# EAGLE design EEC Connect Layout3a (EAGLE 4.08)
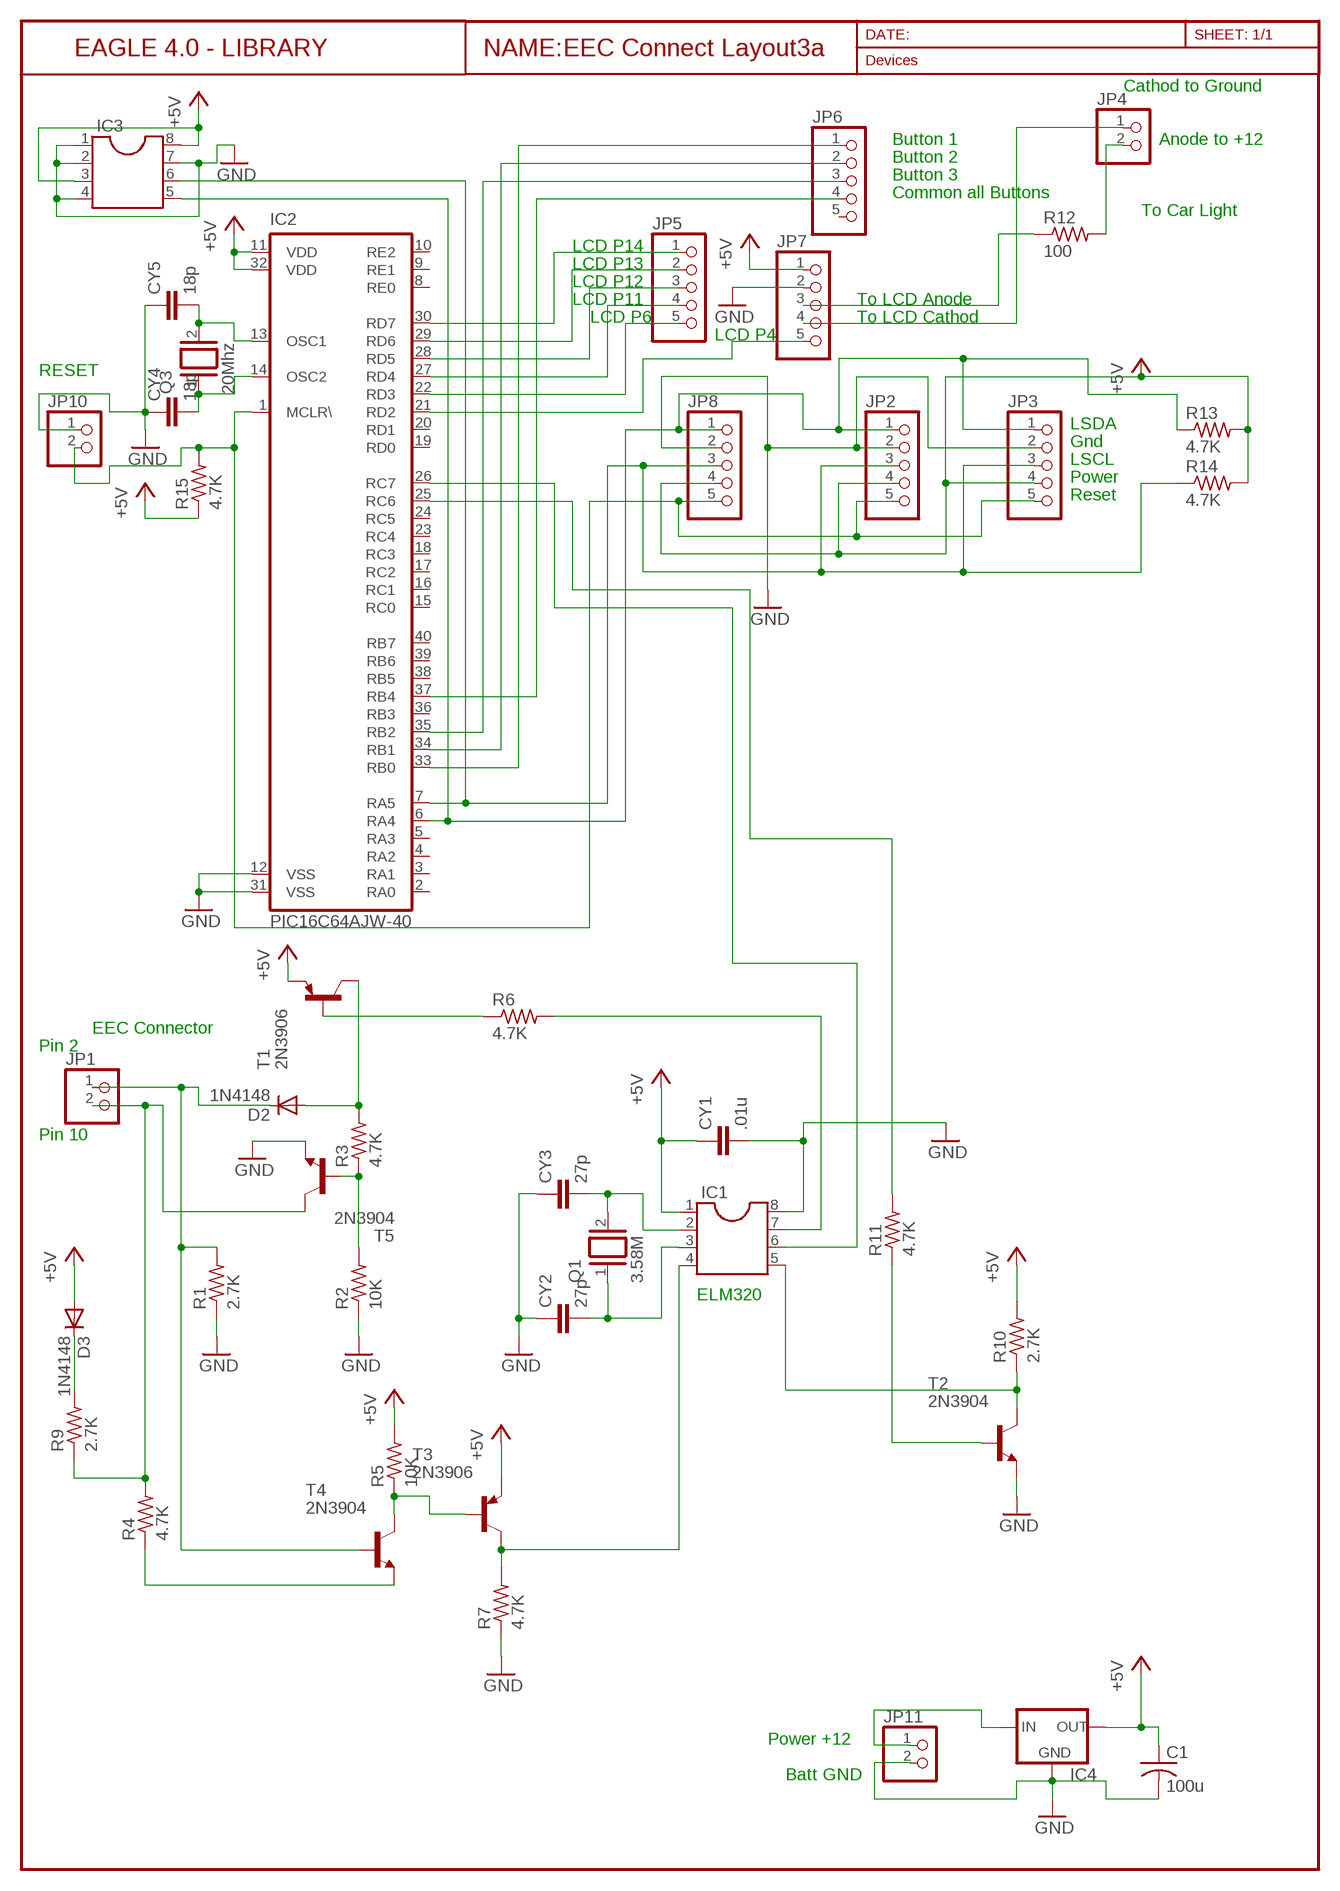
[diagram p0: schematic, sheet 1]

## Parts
C1  100u  C-US050-025X075  [C050-025X075]
CY1  .01u  CYYC7B5  [YC7B5]
CY2  27p  CYYC7B5  [YC7B5]
CY3  27p  CYYC7B5  [YC7B5]
CY4  18p  CYYC7B5  [YC7B5]
CY5  18p  CYYC7B5  [YC7B5]
D2  1N4148  [DO35-10]
D3  1N4148  [DO35-10]
IC1  DIL8  [DIL08]
IC2  PIC16C64AJW-40  [DIL40]
IC3  DIL8  [DIL08]
IC4  78XXL  [78XXL]
JP1  PINHD-1X2  [1X02]
JP2  PINHD-1X5  [1X05]
JP3  PINHD-1X5  [1X05]
JP4  PINHD-1X2  [1X02]
JP5  PINHD-1X5  [1X05]
JP6  PINHD-1X5  [1X05]
JP7  PINHD-1X5  [1X05]
JP8  PINHD-1X5  [1X05]
JP10  PINHD-1X2  [1X02]
JP11  PINHD-1X2  [1X02]
Q1  3.58M  XTAL/S  [QS]
Q3  20Mhz  XTAL/S  [QS]
R1  2.7K  R-US_0207/10  [0207/10]
R2  10K  R-US_0207/10  [0207/10]
R3  4.7K  R-US_0207/10  [0207/10]
R4  4.7K  R-US_0207/10  [0207/10]
R5  10K  R-US_0207/10  [0207/10]
R6  4.7K  R-US_0207/10  [0207/10]
R7  4.7K  R-US_0207/10  [0207/10]
R9  2.7K  R-US_0207/10  [0207/10]
R10  2.7K  R-US_0207/10  [0207/10]
R11  4.7K  R-US_0207/10  [0207/10]
R12  100  R-US_0204/7  [0204/7]
R13  4.7K  R-US_0204/7  [0204/7]
R14  4.7K  R-US_0204/7  [0204/7]
R15  4.7K  R-US_0204/7  [0204/7]
T1  2N3906  [TO92]
T2  2N3904  [TO92]
T3  2N3906  [TO92]
T4  2N3904  [TO92]
T5  2N3904  [TO92]

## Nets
+5V: C1.1 CY1.1 D3.A IC1.1 IC2.11(VDD) IC2.32(VDD) IC3.3 IC3.8 IC4.OUT JP2.4 JP3.4 JP7.1 JP8.4 R5.2 R10.2 R13.2 R14.2 R15.1 T1.3(E) T3.3(E)
GND: C1.2 CY1.2 CY2.1 CY3.1 CY4.1 CY5.1 IC1.8 IC2.12(VSS) IC2.31(VSS) IC3.1 IC3.2 IC3.4 IC3.7 IC4.GND JP2.2 JP3.2 JP7.2 JP8.2 JP10.1 JP11.2 R1.1 R2.1 R7.1 T2.3(E) T5.3(E)
N$1: CY5.2 IC2.13(OSC1) Q3.2
N$2: R2.2 R3.1 T5.2(B)
N$3: D2.C JP1.1 R1.2 T4.2(B)
N$4: IC1.4 R7.2 T3.1(C)
N$5: CY3.2 IC1.2 Q1.2
N$6: CY2.2 IC1.3 Q1.1
N$7: JP4.1 JP7.4
N$8: CY4.2 IC2.14(OSC2) Q3.1
N$9: D3.C R9.2
N$10: R4.1 T4.3(E)
N$11: R5.1 T3.2(B) T4.1(C)
N$12: IC2.37(RB4) JP6.4
N$13: JP4.2 R12.2
N$14: IC2.6(RA4) IC3.5 JP2.1 JP3.1 JP8.1 R13.1
N$15: IC1.7 R6.2
N$16: R6.1 T1.2(B)
N$17: D2.A R3.2 T1.1(C)
N$18: IC2.33(RB0) JP6.1
N$19: JP1.2 R4.2 R9.1 T5.1(C)
N$20: JP7.3 R12.1
N$21: IC2.34(RB1) JP6.2
N$23: IC2.7(RA5) IC3.6 JP2.3 JP3.3 JP8.3 R14.1
N$24: IC2.35(RB2) JP6.3
N$25: IC2.30(RD7) JP5.1
N$27: IC2.29(RD6) JP5.2
N$28: IC2.28(RD5) JP5.3
N$30: IC2.27(RD4) JP5.4
N$31: IC2.22(RD3) JP5.5
N$33: IC2.1(MCLR\) JP2.5 JP3.5 JP8.5 JP10.2 R15.2
N$35: IC2.21(RD2) JP7.5
N$36: R11.1 T2.2(B)
N$40: IC1.5 R10.1 T2.1(C)
N$42: IC4.IN JP11.1
N$45: IC2.25(RC6) R11.2
N$46: IC1.6 IC2.26(RC7)
Unconnected: IC2.2(RA0) IC2.3(RA1) IC2.4(RA2) IC2.5(RA3) IC2.8(RE0) IC2.9(RE1) IC2.10(RE2) IC2.15(RC0) IC2.16(RC1) IC2.17(RC2) IC2.18(RC3) IC2.19(RD0) IC2.20(RD1) IC2.23(RC4) IC2.24(RC5) IC2.36(RB3) IC2.38(RB5) IC2.39(RB6) IC2.40(RB7) JP6.5

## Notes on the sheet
- Cathod to Ground
- Button 1 | Anode to +12
- Button 2
- Button 3
- Common all Buttons
- To Car Light
- LCD P14
- LCD P13
- LCD P12
- LCD P11 | To LCD Anode
- LCD P6 | To LCD Cathod
- LCD P4
- RESET
- LSDA
- Gnd
- LSCL
- Power
- Reset
- EEC Connector
- Pin 2
- Pin 10
- ELM320
- Power +12
- Batt GND

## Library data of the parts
C1 = rcl:C-US: CAPACITOR, American symbol
CY1-CY5 = rcl:CY: Y CAPACITOR
D2 D3 = diode:1N4148: DIODE
IC1 IC3 = dil:DIL8: SOCKET Dual In Line
IC2 = microchip:PIC16C*?-40: MICROCONTROLLER 8-Bit CMOS Pin compatible: PIC16CR64, PIC16C64A, PIC16C65A, PIC16CR65, PIC16C67, PIC16C74A, PIC16C77
IC4 = v-reg:78XXL: VOLTAGE REGULATOR
JP1 JP4 JP10 JP11 = pinhead:PINHD-1X2: PIN HEADER
JP2 JP3 JP5-JP8 = pinhead:PINHD-1X5: PIN HEADER
Q1 Q3 = special:XTAL/S: CRYSTAL
R1-R7 R9-R15 = rcl:R-US_: RESISTOR, American symbol
T1 T3 = transistor-pnp:2N3906: PNP TRANSISTOR
T2 T4 T5 = transistor-npn:2N3904: NPN TRANSISTOR

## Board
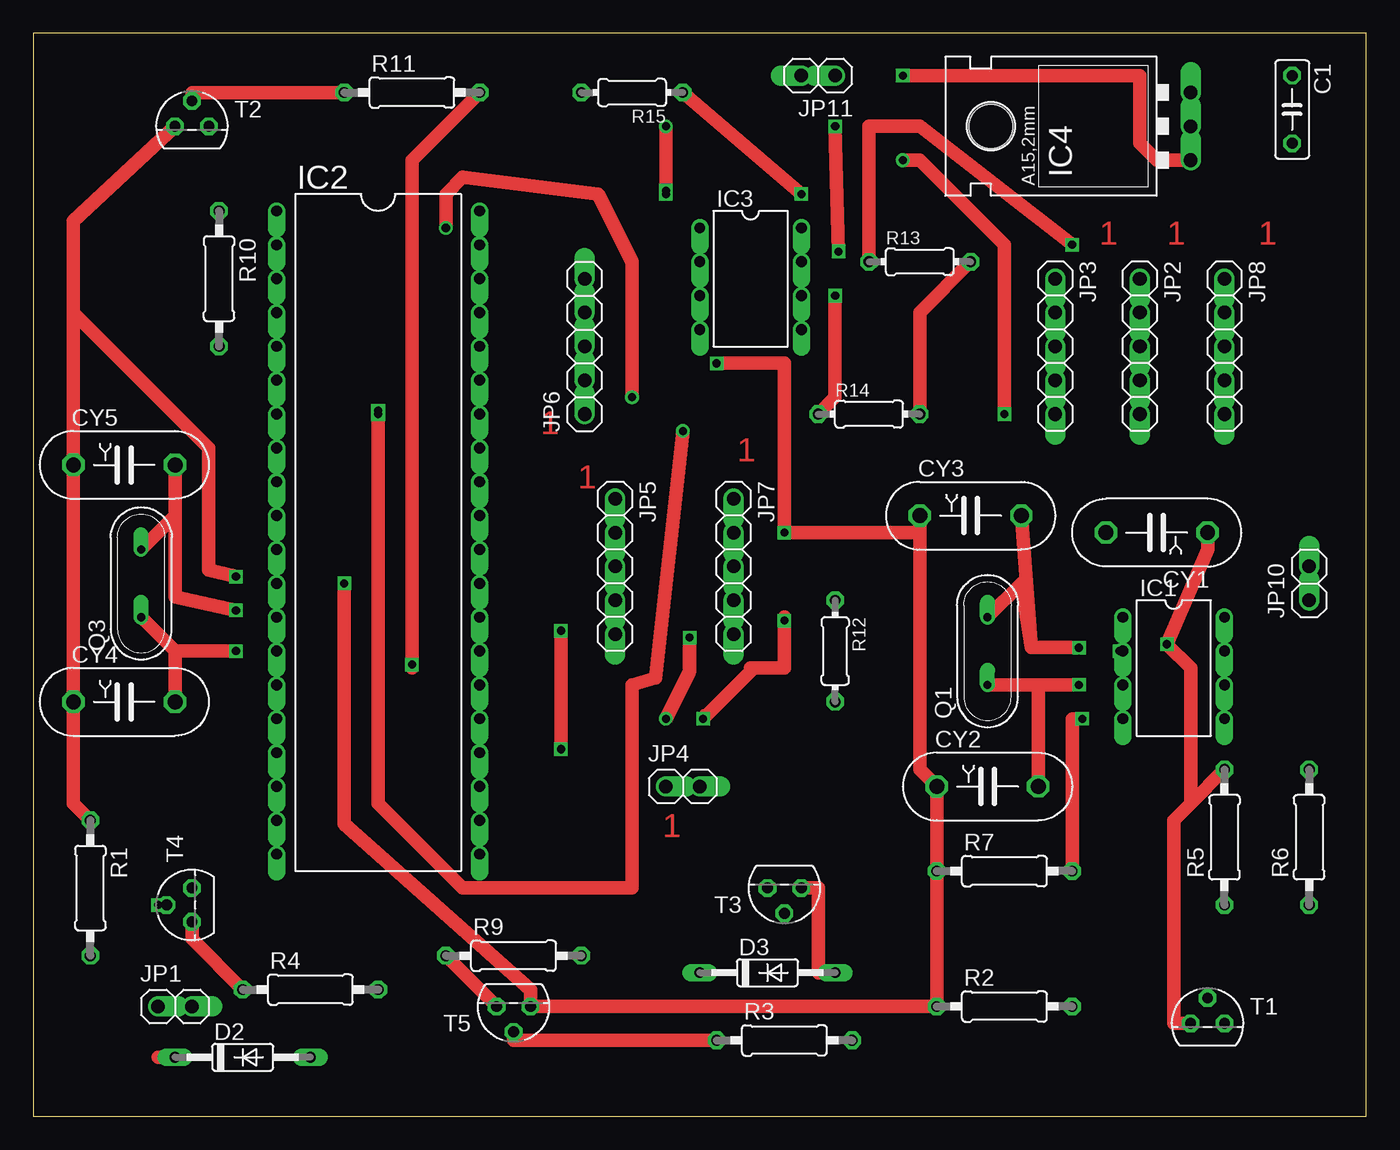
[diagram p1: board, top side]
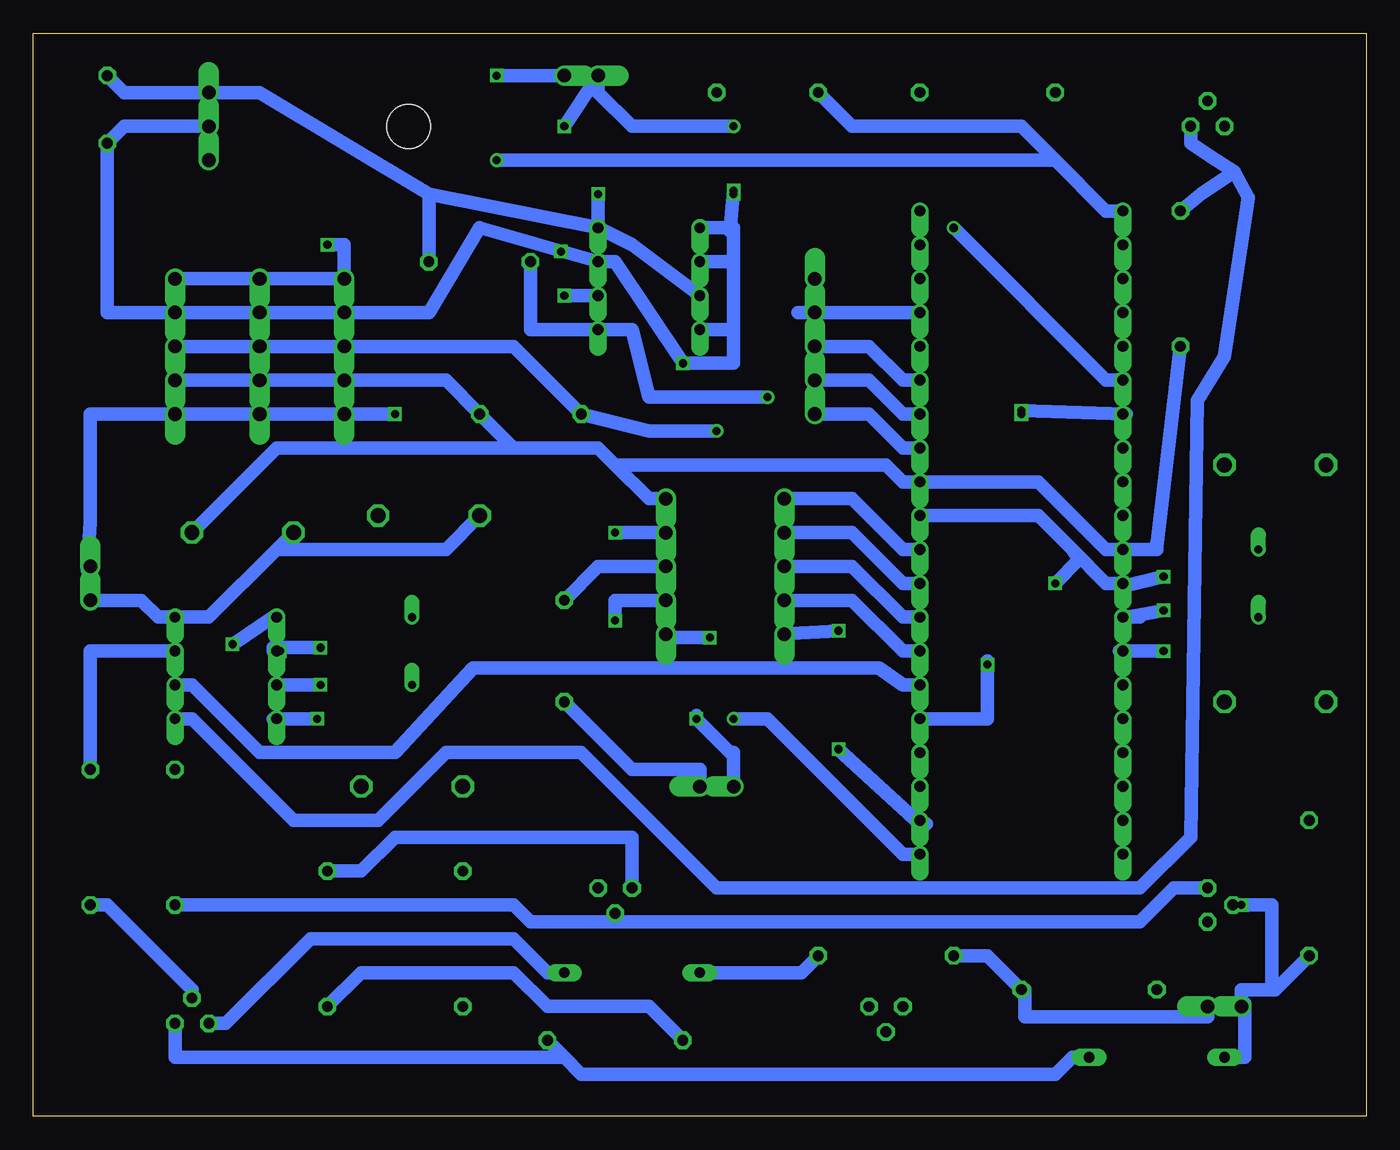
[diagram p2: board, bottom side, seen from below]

Size 100 x 81.27 mm. Coordinates in mm from the lower left corner, seen from the top.
Outline: 0,0 100,0 100,81.27 0,81.27 0,0
Copper layers used: Top, Bottom

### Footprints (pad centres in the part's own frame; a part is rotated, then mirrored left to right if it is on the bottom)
C050-025X075 = drill 0.813 octagon: 1 -2.54,0; 2 2.54,0
YC7B5 = drill 1.118 octagon: 1 -3.81,0; 2 3.81,0
DO35-10 = drill 0.813 long: A 5.08,0; C -5.08,0
DIL08 = drill 0.813 offset: 1 -3.81,-3.81; 2 -1.27,-3.81; 3 1.27,-3.81; 4 3.81,-3.81; 5 3.81,3.81; 6 1.27,3.81; 7 -1.27,3.81; 8 -3.81,3.81
DIL40 = drill 0.813 offset: 1 -24.13,-7.62; 2 -21.59,-7.62; 3 -19.05,-7.62; 4 -16.51,-7.62; 5 -13.97,-7.62; 6 -11.43,-7.62; 7 -8.89,-7.62; 8 -6.35,-7.62; 9 -3.81,-7.62; 10 -1.27,-7.62; 11 1.27,-7.62; 12 3.81,-7.62; 13 6.35,-7.62; 14 8.89,-7.62; 15 11.43,-7.62; 16 13.97,-7.62; 17 16.51,-7.62; 18 19.05,-7.62; 19 21.59,-7.62; 20 24.13,-7.62; 21 24.13,7.62; 22 21.59,7.62; 23 19.05,7.62; 24 16.51,7.62; 25 13.97,7.62; 26 11.43,7.62; 27 8.89,7.62; 28 6.35,7.62; 29 3.81,7.62; 30 1.27,7.62; 31 -1.27,7.62; 32 -3.81,7.62; 33 -6.35,7.62; 34 -8.89,7.62; 35 -11.43,7.62; 36 -13.97,7.62; 37 -16.51,7.62; 38 -19.05,7.62; 39 -21.59,7.62; 40 -24.13,7.62
78XXL = drill 1.016 offset: GND 0,-3.81; IN -2.54,-3.81; OUT 2.54,-3.81 | hole 3.302: 0,11.176
1X02 = drill 1.016 offset: 1 -1.27,0; 2 1.27,0
1X05 = drill 1.016 offset: 1 -5.08,0; 2 -2.54,0; 3 0,0; 4 2.54,0; 5 5.08,0
QS = drill 0.61 offset: 1 -2.54,0; 2 2.54,0
0207/10 = drill 0.813 octagon: 1 -5.08,0; 2 5.08,0
0204/7 = drill 0.813 octagon: 1 -3.81,0; 2 3.81,0
TO92 = drill 0.813 octagon: 1 1.27,0; 2 0,1.905; 3 -1.27,0

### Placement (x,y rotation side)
C1  94.45,75.56 270 top
CY1  84.29,43.81 180 top
CY2  71.59,24.76 0 top
CY3  70.32,45.08 0 top
CY4  6.82,31.11 0 top
CY5  6.82,48.89 0 top
D2  15.71,4.44 0 top
D3  55.08,10.79 0 top
IC1  85.56,33.65 270 top
IC2  25.87,43.81 270 top
IC3  53.81,62.86 270 top
IC4  83.02,74.29 90 top
JP1  10.63,8.25 0 top
JP2  83.02,57.78 270 top
JP3  76.67,57.78 270 top
JP4  48.73,24.76 0 top
JP5  43.65,41.27 270 top
JP6  41.36,57.78 90 top
JP7  52.54,41.27 270 top
JP8  89.37,57.78 270 top
JP10  95.72,40 90 top
JP11  58.89,78.1 180 top
Q1  71.59,34.92 90 top
Q3  8.09,40 90 top
R1  4.28,17.14 270 top
R2  72.86,8.25 0 top
R3  56.35,5.71 0 top
R4  20.79,9.52 0 top
R5  89.37,20.95 90 top
R6  95.72,20.95 90 top
R7  72.86,18.41 0 top
R9  36.03,12.06 0 top
R10  13.93,62.86 270 top
R11  28.41,76.83 0 top
R12  60.16,34.92 270 top
R13  66.51,64.13 0 top
R14  62.7,52.7 0 top
R15  44.92,76.83 180 top
T1  88.1,6.98 0 top
T2  11.9,74.29 0 top
T3  56.35,17.14 180 top
T4  11.9,15.87 90 top
T5  36.03,8.25 180 top

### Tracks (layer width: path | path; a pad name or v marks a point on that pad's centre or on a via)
+5V  (via drill 0.61)
  Top 1.016: CY1.1 88.1,42.54 v85.05,35.43 86.83,33.65 86.83,23.49 | T3.3 58.89,17.14 58.89,10.79 D3.A | T1.3 85.56,6.98 85.56,22.22 86.83,23.49 | 86.83,23.49 R5.2 | v57.62,69.21 R15.1 | R13.2 66.51,60.32 R14.2
  Bottom 1.016: T1.3 85.56,6.98 79.21,13.33 63.97,13.33 61.43,10.79 D3.A | IC3.3 55.08,65.4 IC3.8 | C1.1 93.18,76.83 IC4.OUT 83.02,76.83 70.32,69.21 | 56.35,48.89 57.62,50.16 63.97,50.16 | 56.35,48.89 53.81,46.35 JP7.1 | 63.97,50.16 R14.2 69.05,55.24 JP3.4 JP2.4 JP8.4 | R13.2 70.32,69.21 | 70.32,69.21 IC3.8 | 56.35,48.89 36.03,48.89 34.76,47.62 IC2.32 24.6,47.62 19.52,42.54 IC2.11 15.71,42.54 15.71,42.79 | CY1.1 81.75,50.16 63.97,50.16 | IC3.8 v57.62,69.21 | IC1.1 82,37.46 v85.05,35.43 | 15.71,42.79 15.71,43.05 | 15.71,42.79 R10.2
GND  (via drill 0.61)
  Top 1.016: R1.1 3.01,23.49 CY4.1 CY5.1 3.01,60.32 | T2.3 3.01,67.18 3.01,60.32 | 3.01,60.32 13.17,50.16 13.17,41.02 v15.2,40.51 | 66.51,43.81 v56.35,43.81 56.35,56.51 v51.27,56.51 | 66.51,43.81 CY3.1 | 66.51,43.81 66.51,26.03 CY2.1 R7.1 R2.1 T5.3 37.3,9.52 23.33,21.97 v23.33,40 | v47.46,69.46 v47.46,74.29 | v60.16,74.29 60.41,64.89
  Bottom 1.016: 22.06,42.54 19.52,40 IC2.12 18.25,39.75 v15.2,40.51 | 22.06,42.54 24.6,45.08 IC2.31 | IC4.GND 93.18,74.29 C1.2 94.45,60.32 JP8.2 JP2.2 JP3.2 70.32,60.32 66.51,66.67 IC3.7 56.35,64.13 v51.27,56.51 47.46,56.51 47.46,59.05 | JP10.1 91.91,38.73 90.64,37.46 IC1.8 86.83,37.46 81.75,42.54 | 81.75,42.54 CY1.2 | CY3.1 69.05,42.54 81.75,42.54 | v60.16,74.29 JP11.2 57.62,76.83 55.08,74.29 v47.46,74.29 | 47.46,66.67 IC3.1 | 47.46,64.13 47.46,66.67 | 47.46,59.05 IC3.4 | 47.46,64.13 IC3.2 | 47.46,59.05 47.46,64.13 | v47.46,69.46 47.71,66.42 47.46,66.67 | v23.33,40 21.55,41.78 22.06,42.54 | v56.35,43.81 JP7.2
N$1  (via drill 0.61)
  Top 1.016: 10.63,45.08 Q3.2 | 10.63,45.08 CY5.2 | 10.63,45.08 10.63,38.98 v15.2,37.97
  Bottom 1.016: 16.98,37.46 18,37.46 17.01,37.64 | v15.2,37.97 17.01,37.64 | 16.98,37.46 IC2.13 | 17.01,37.64 16.98,37.46
N$2
  Top 1.016: R3.1 36.03,5.71 T5.2
  Bottom 1.016: R2.2 75.4,10.79 63.97,10.79 61.43,8.25 53.81,8.25 R3.1
N$3  (via drill 0.61)
  Top 1.016: D2.C 9.36,4.44 | v9.36,15.87 T4.2
  Bottom 1.016: R1.2 6.82,9.52 7.07,9.52 | 7.07,9.52 9.36,9.52 JP1.1 9.11,8.25 | v9.36,15.87 7.07,15.87 7.07,9.52 | 9.11,8.25 9.11,8.5 | 9.11,8.25 9.11,4.44 D2.C
N$4  (via drill 0.61)
  Top 1.016: R7.2 77.94,29.84 v78.7,29.84
  Bottom 1.016: T3.1 55.08,20.95 72.86,20.95 75.4,18.41 R7.2 | 82,29.84 IC1.4 v78.7,29.84
N$5  (via drill 0.61)
  Top 1.016: Q1.2 74.13,40 74.89,35.17 | 74.89,35.17 CY3.2 | v81.5,34.92 IC1.2 | 74.89,35.17 v78.45,35.17
  Bottom 1.016: v81.5,34.92 82,34.92 82,35.17 v78.45,35.17
N$6  (via drill 0.61)
  Top 1.016: 75.4,32.38 Q1.1 | 75.4,32.38 v78.45,32.38 | CY2.2 75.4,32.38
  Bottom 1.016: v78.45,32.38 IC1.3 81.75,32.13
N$7  (via drill 0.61)
  Top 0.406: 53.81,33.65 53.81,33.9 | v50.25,29.84 50.25,30.35
  Top 1.016: 54.06,33.65 56.35,33.65 v56.35,37.21 56.35,37.46 | v50.25,29.84 54.06,33.65 | 54.06,33.65 53.81,33.65
  Bottom 0.406: 47.46,27.05 47.21,27.3 47.46,27.3 47.71,27.3
  Bottom 1.016: 56.35,37.46 v56.35,37.21 56.35,38.73 JP7.4 | 47.46,27.05 47.46,27.3 JP4.1 | 47.71,27.3 v50.25,29.84 50.25,30.09
N$8  (via drill 0.61)
  Top 1.016: 10.63,34.92 Q3.1 | CY4.2 10.63,34.92 | 10.63,34.92 v15.2,34.92
  Bottom 1.016: 18.5,34.92 IC2.14 v15.2,34.92
N$9
  Bottom 1.016: R9.2 42.38,10.79 D3.C
N$10
  Top 1.016: R4.1 11.9,13.33 T4.3
N$11
  Bottom 1.016: 56.35,14.6 62.7,14.6 63.97,15.87 R5.1 | T4.1 14.44,17.14 16.98,14.6 56.35,14.6 | 56.35,14.6 T3.2
N$12
  Bottom 1.016: 42.63,60.32 JP6.4 IC2.37
N$13
  Bottom 1.016: R12.2 55.08,26.03 50,26.03 JP4.2
N$14  (via drill 0.61)
  Top 1.016: v30.95,66.67 30.95,69.21 32.22,70.48 42.38,69.21 44.92,64.13 v44.92,53.97 | v77.94,65.4 66.51,74.29 62.7,74.29 R13.1
  Bottom 1.016: v30.95,66.67 19.52,55.24 IC2.6 | v44.92,53.97 53.81,53.97 55.08,59.05 IC3.5 62.7,59.05 R13.1 | JP8.1 JP2.1 JP3.1 76.67,65.4 v77.94,65.4
N$15
  Bottom 1.016: R6.2 95.72,34.92 IC1.7
N$16
  Bottom 1.016: R6.1 94.45,15.87 88.1,9.52 T1.2
N$17
  Bottom 1.016: 60.16,4.44 R3.2 | 60.16,4.44 58.89,3.17 23.33,3.17 22.06,4.44 D2.A | T1.1 89.37,4.44 60.16,4.44
N$18
  Bottom 1.016: IC2.33 34.76,50.16 37.3,52.7 JP6.1
N$19
  Top 1.016: R9.1 T5.1
  Bottom 1.016: R9.1 28.41,12.06 R4.2 25.62,9.52 25.62,7.49 11.9,7.49 JP1.2
N$20
  Bottom 1.016: R12.1 57.62,41.27 JP7.3
N$21
  Bottom 1.016: IC2.34 34.76,52.7 37.3,55.24 JP6.2
N$22  (via drill 0.61)
  other vias: 60.41,64.89
N$23  (via drill 0.61)
  Top 1.016: v48.73,51.43 46.7,32.89 44.92,32.38 44.92,17.14 32.22,17.14 25.87,23.49 v25.87,52.95 | v60.16,61.59 60.16,53.97 R14.1
  Bottom 1.016: v48.73,51.43 53.81,51.43 R14.1 63.97,57.78 JP3.3 JP2.3 JP8.3 | v60.16,61.59 IC3.6 | IC2.7 18,52.7 v25.87,52.95
N$24
  Bottom 1.016: IC2.35 34.76,55.24 37.3,57.78 JP6.3
N$25
  Bottom 1.016: IC2.30 34.76,42.54 38.57,46.35 JP5.1
N$26  (via drill 0.61)
  other vias: 47.46,69.21
N$27
  Bottom 1.016: IC2.29 34.76,40 38.57,43.81 JP5.2
N$28
  Bottom 1.016: IC2.28 34.76,37.46 38.57,41.27 JP5.3
N$29  (via drill 0.61)
  other vias: 25.87,52.7
N$30
  Bottom 1.016: IC2.27 34.76,34.92 38.57,38.73 JP5.4
N$31  (via drill 0.61)
  Top 1.016: v39.59,27.55 v39.59,36.44
  Bottom 1.016: v39.59,27.55 33.49,21.97 33.62,22.09 | 32.98,21.97 33.62,22.09 | 33.62,22.09 IC2.22 | JP5.5 43.9,36.19 v39.59,36.44
N$32  (via drill 0.61)
  other vias: 15.2,40.51
N$33  (via drill 0.61)
  Top 1.016: v72.86,52.7 72.86,65.4 66.51,71.75 v65.24,71.75
  Bottom 1.016: 23.33,71.75 25.87,74.29 38.57,74.29 R15.2 | 23.33,71.75 19.52,67.94 IC2.1 | 23.33,71.75 v65.24,71.75 | v72.86,52.7 JP3.5 JP2.5 JP8.5 95.72,52.7 95.72,44.57 95.97,41.02 95.47,41.27 JP10.2
N$34  (via drill 0.61)
  other vias: 15.2,37.97
N$35  (via drill 0.61)
  Top 1.016: v47.46,29.84 49.24,33.4 v49.24,35.94
  Bottom 1.016: v47.46,29.84 44.92,29.84 34.76,19.68 IC2.21 | JP7.5 52.79,36.19 52.79,35.94 v49.24,35.94
N$36
  Top 1.016: R11.1 11.9,76.83 T2.2
N$37  (via drill 0.61)
  other vias: 78.45,35.17
N$38  (via drill 0.61)
  other vias: 50.25,29.84
N$40
  Bottom 1.016: R10.1 12.41,69.21 9.91,70.89 | 9.91,70.89 11.65,72 13.17,73.02 T2.1 | IC1.5 88.1,29.84 80.48,22.22 74.13,22.22 69.05,27.3 58.89,27.3 48.73,17.14 16.98,17.14 13.17,20.95 12.66,53.71 10.63,57.02 8.85,68.96 9.91,70.89
N$42  (via drill 0.61)
  Top 1.016: v65.24,78.1 83.02,78.1 83.02,73.02 84.29,71.75 IC4.IN
  Bottom 1.016: JP11.1 v65.24,78.1
N$45  (via drill 0.61)
  Top 1.016: 28.41,33.65 v28.41,33.9 28.41,71.75 R11.2
  Bottom 1.016: 28.41,34.16 v28.41,33.9 28.41,29.84 IC2.25
N$46
  Bottom 1.016: IC2.26 34.76,32.38 36.54,33.65 67.02,33.65 72.86,27.3 83.02,27.3 88.1,32.38 IC1.6

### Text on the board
Top: 1 | 1 | 1 | 1 | 1 | 1 | 1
